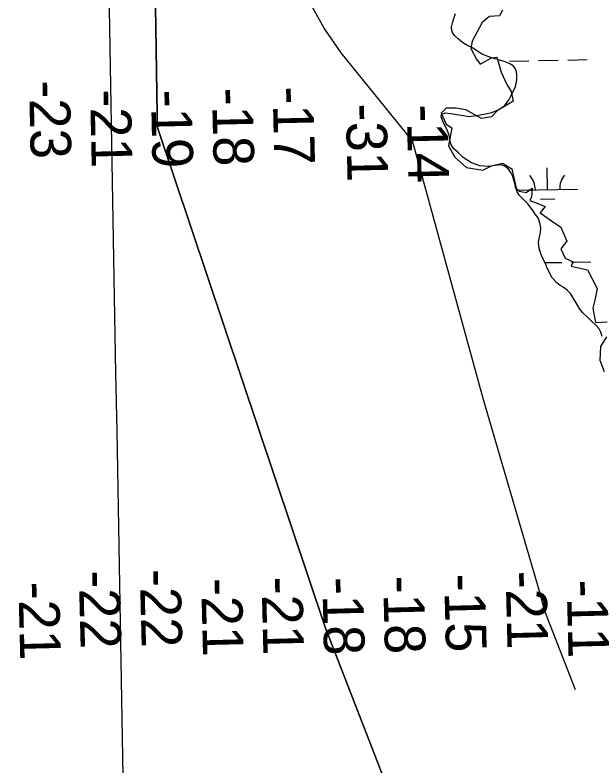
# Model space of a CAD drawing. Extents: x 3925854 to 3964121, y 224593 to 250589.
# Drawn here: x 3945726 to 3946690, y 239895 to 241130 of the extents above; entities that cross this region are included whole.
import ezdxf

# ---------------------------------------------------------------- set-up
doc = ezdxf.new("R2010")
doc.units = 0
for name, color, linetype in [('V-GRID-MAJR', 7, 'Continuous'), ('V-RIVR-EDGE', 7, 'Continuous'), ('V-RIVR-RANG', 7, 'Continuous'), ('V-TOPO-DPTH', 7, 'Continuous'), ('V-TOPO-MINR', 7, 'Continuous'), ('V-WETL-SWMP', 7, 'Continuous')]:
    doc.layers.add(name, color=color, linetype=linetype)

msp = doc.modelspace()

# ---------------------------------------------------------------- linework, layer by layer
at = {"layer": 'V-GRID-MAJR'}
msp.add_spline([(3946078.266, 230317.988), (3945968.142, 236374.431), (3945857.954, 242434.345), (3945747.767, 248494.247), (3945747.704, 248497.728)], degree=3, dxfattribs=at)
at = {"layer": 'V-RIVR-EDGE'}
for points in [[(3946528.071, 241138.491), (3946523.322, 241128.993), (3946506.701, 241127.806), (3946494.829, 241118.308), (3946486.519, 241102.874), (3946478.208, 241087.441), (3946475.834, 241075.568), (3946485.331, 241057.76), (3946491.267, 241049.45), (3946510.263, 241060.135), (3946518.573, 241061.322), (3946525.697, 241036.39), (3946535.194, 241016.208), (3946542.318, 241004.336), (3946545.879, 240988.902), (3946534.007, 240981.779), (3946519.761, 240973.468), (3946510.263, 240962.783), (3946493.642, 240960.409), (3946467.523, 240974.655), (3946452.089, 240977.03), (3946435.468, 240977.03), (3946427.158, 240968.719), (3946435.468, 240950.911), (3946444.966, 240944.975), (3946439.03, 240915.295), (3946449.715, 240896.299), (3946468.71, 240879.678), (3946496.016, 240874.93), (3946510.263, 240882.053), (3946528.071, 240886.802), (3946543.505, 240877.304), (3946550.628, 240845.249), (3946555.377, 240840.5), (3946567.249, 240838.126), (3946576.747, 240845.249), (3946575.56, 240831.003), (3946573.185, 240825.067), (3946586.244, 240820.318), (3946598.117, 240815.569), (3946589.806, 240804.884), (3946608.801, 240791.825), (3946624.235, 240781.14), (3946633.733, 240758.583), (3946624.235, 240745.523), (3946631.359, 240730.09), (3946644.418, 240724.154), (3946640.856, 240717.03), (3946668.162, 240711.094), (3946683.596, 240680.227), (3946680.034, 240661.231), (3946676.473, 240648.172), (3946681.221, 240624.428), (3946700.217, 240625.615)], [(3946699.03, 240600.683), (3946689.532, 240585.25), (3946688.345, 240562.693), (3946695.468, 240543.697)]]:
    msp.add_lwpolyline(points, dxfattribs=at)
at = {"layer": 'V-TOPO-DPTH'}
for points in [[(3945561.622, 241892.679), (3946062.984, 241827.884), (3946041.65, 241799.711), (3946034.667, 241791.437), (3946027.172, 241783.716), (3946018.908, 241776.824), (3946010.131, 241770.486), (3946002.292, 241763.746), (3945995.961, 241756.07), (3945991.893, 241746.99), (3945989.334, 241736.974), (3945972.697, 241589.953), (3945964.765, 241505.52), (3945958.978, 241420.981), (3945956.408, 241336.283), (3945955.983, 241251.48), (3945959.963, 240967.209), (3945960.313, 240954.99), (3945960.773, 240945.447)], [(3945960.773, 240945.447), (3946236.204, 240123.225), (3946535.235, 239352.689)]]:
    msp.add_lwpolyline(points, dxfattribs=at)
at = {"layer": 'V-TOPO-MINR'}
for points in [[(3946648.337, 240019.971), (3946597.827, 240149.337), (3946594.009, 240163.885), (3946589.966, 240178.376), (3946496.441, 240499.195), (3946380.336, 240923.257), (3946379.763, 240924.048), (3946262.891, 241068.077), (3946234.846, 241108.648), (3946211.299, 241151.274), (3946194.498, 241196.982), (3946182.195, 241244.744), (3946174.874, 241294.247), (3946169.436, 241343.901), (3946166.824, 241393.785), (3946166.096, 241443.82), (3946169.598, 241696.449), (3946170.621, 241726.329), (3946172.45, 241756.143), (3946175.49, 241785.857), (3946179.337, 241815.506), (3946185.185, 241844.658), (3946192.851, 241873.227), (3946196.052, 241881.757)], [(3945960.773, 240945.447), (3945960.313, 240954.99), (3945959.963, 240967.209), (3945955.983, 241251.48), (3945956.408, 241336.283), (3945958.978, 241420.981), (3945964.765, 241505.52), (3945972.697, 241589.953), (3945989.334, 241736.974), (3945991.893, 241746.99), (3945995.961, 241756.07), (3946002.292, 241763.746), (3946010.131, 241770.486), (3946018.908, 241776.824), (3946027.172, 241783.716), (3946034.667, 241791.437), (3946041.65, 241799.711), (3946062.984, 241827.884)], [(3947132.294, 237888.663), (3946552.118, 239309.184), (3946236.204, 240123.225), (3945960.773, 240945.447)]]:
    msp.add_lwpolyline(points, dxfattribs=at)
at = {"layer": 'V-WETL-SWMP'}
for p, q in [((3946539.457, 241054.628), (3946571.452, 241055.21)), ((3946587.449, 241055.5), (3946619.444, 241056.082)), ((3946635.441, 241056.373), (3946667.436, 241056.955)), ((3946602.157, 240843.129), (3946601.502, 240879.123)), ((3946552.165, 240842.22), (3946652.148, 240844.038)), ((3946590.439, 240827.482), (3946614.435, 240827.918)), ((3946597.783, 240722.958), (3946625.492, 240723.462)), ((3946641.489, 240723.753), (3946673.484, 240724.335))]:
    msp.add_line(p, q, dxfattribs=at)
for points in [[(3946485.238, 240965.018), (3946500.194, 240967.687), (3946510.708, 240969.999), (3946521.244, 240974.428), (3946531.501, 240981.181), (3946538.868, 240991.292), (3946542.467, 240997.911), (3946549.479, 241012.666), (3946551.411, 241023.942), (3946551.904, 241032.511), (3946551.145, 241037.158), (3946549.477, 241041.614), (3946545.394, 241046.699), (3946540.084, 241050.184), (3946532.25, 241053.392), (3946523.503, 241056.105), (3946515.254, 241058.208), (3946503.895, 241061.957), (3946494.454, 241065.787), (3946487.644, 241070.497), (3946478.831, 241076.64), (3946468.591, 241081.286), (3946462.279, 241085.386), (3946455.877, 241090.495), (3946449.085, 241096.92), (3946445.806, 241101.695), (3946444.627, 241104.733), (3946444.288, 241110.889), (3946445.767, 241117.43), (3946448.683, 241126.276), (3946451.071, 241132.807)], [(3946691.867, 240601.195), (3946689.723, 240608.378), (3946686.858, 240614.157), (3946681.375, 240620.367), (3946675.577, 240625.47), (3946668.191, 240632.91), (3946660.298, 240640.254), (3946655.218, 240646.359), (3946649.172, 240656.71), (3946644.913, 240664.218), (3946639.751, 240672.24), (3946634.861, 240677.233), (3946627.854, 240682.45), (3946622.841, 240685.326), (3946617.52, 240689.678), (3946610.003, 240698.168), (3946601.675, 240714.07), (3946598.03, 240722.479), (3946594.372, 240729.578), (3946591.027, 240737.682), (3946588.296, 240746.687), (3946587.493, 240756.782), (3946589.098, 240765.641), (3946590.678, 240772.08), (3946591.264, 240780.042), (3946589.539, 240788.734), (3946586.598, 240796.935), (3946582.515, 240801.92), (3946576.752, 240810.351), (3946569.589, 240819.907), (3946562.305, 240827.547), (3946556.112, 240833.361), (3946552.139, 240839.353), (3946549.395, 240847.047), (3946548.454, 240853.613), (3946546.996, 240858.873), (3946544.838, 240864.746), (3946541.676, 240871.133), (3946537.901, 240876.72), (3946532.603, 240881.313), (3946525.77, 240883.805), (3946515.873, 240882.596), (3946504.46, 240881.101), (3946491.059, 240882.45), (3946477.087, 240887.134), (3946463.463, 240896.152), (3946455.671, 240903.394), (3946448.178, 240910.33), (3946443.708, 240916.933), (3946441.66, 240923.712), (3946440.918, 240929.973), (3946439.359, 240935.235), (3946436.902, 240941.514), (3946433.74, 240947.8), (3946429.705, 240955.548), (3946427.179, 240962.937), (3946427.519, 240966.484), (3946434.043, 240969.281), (3946443.517, 240968.578), (3946452.678, 240966.869), (3946463.954, 240964.835), (3946472.915, 240963.33), (3946485.238, 240965.018)]]:
    msp.add_lwpolyline(points, dxfattribs=at)
for centre, start, end in [((3946546.914, 240842.599), 0.269879, 41.813537), ((3946657.382, 240844.608), 140.269876, 181.813534)]:
    msp.add_arc(centre, 35.246, start, end, dxfattribs=at)

# ---------------------------------------------------------------- texts
at = {"layer": 'V-RIVR-RANG'}
for s, rotation, p in [('-23', 271.263028, (3945749.366, 241022.34)), ('-21', 271.263028, (3945849.714, 241007.659)), ('-18', 271.263028, (3946050.205, 241010.219)), ('-17', 271.263028, (3946149.981, 241012.422)), ('-19', 271.263028, (3945949.853, 241006.957)), ('-31', 271.263028, (3946270.422, 240984.376)), ('-14', 271.263028, (3946370.479, 240982.888)), ('-22', 271.447, (3945831.081, 240216.17)), ('-22', 271.447, (3945931.46, 240218.228)), ('-21', 271.447, (3946131.638, 240205.711)), ('-18', 271.447, (3946231.577, 240205.386)), ('-18', 271.447, (3946331.656, 240207.438)), ('-15', 271.447, (3946432.008, 240210.55)), ('-21', 271.447, (3946533.107, 240215.375)), ('-21', 271.447, (3945731.722, 240197.511)), ('-21', 271.447, (3946032.359, 240203.675)), ('-11', 271.447, (3946633.502, 240201.024))]:
    msp.add_text(s, height=67, rotation=rotation, dxfattribs=at).set_placement(p)

doc.saveas('drawing.dxf')
